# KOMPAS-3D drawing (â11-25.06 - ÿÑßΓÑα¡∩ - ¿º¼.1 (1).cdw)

Views: Вид 1, Выносной элемент
Referenced files in C:\Users\Konstruktor\Documents\Евстигнеева\Архив чертежей\Изделия\Г11-24\: Г11-24.06 - Шестерня.cdw
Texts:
  Шестерня
  Евстигнеева Г.А.
  НПП "Гидропривод"
  Радиус развернутости
  эвольвенты в начале
  рабочего участка профиля
  Допуск на погрешность
  направления зуба
  Контролировать
  при отсутствии
  обкатки с
  измерительной
  шестерней
  Допуск на
  колебание
  измерительного
  межосевого
  расстояния
  Допуск на колебание длины
  общей нормали
  Длина общей нормали
  Делительный диаметр
  Диаметр начальной окружности
  Степень точности
  по ГОСТ 1643-81
  Коэффициент смещения
  Исходный контур
  Число зубьев
  Модуль
  Отклонение
  основного
  шага
  погрешность
  профиля зуба
  радиальное
  биение
  зубчатого
  венца
  На одном
  зубе
  За оборот
  колеса
  f '' pt
  F vw
  ГОСТ 13755-81
  Н,мм
  Номин.
  Пред. отк.
  Таблица параметров
  47...52 HRC Э . Закалка изотермическая.
  Допускается контроль по суммарному пятну контакта с зубьми
  измерительной шестерни:
  по высоте не менее 30%;
  по длине не менее  40%.
  * Размеры для справок.
  Острые кромки скруглить R 0,1 тах.
  gliv
  Евстигнеева
  Сталь 40Х ГОСТ 4543-71
  г.Ярославль
Dimensions and other numbers on the sheet: 8; 0,4; 0,02; 0,8; 2,5; 0,01; 8,57464; 0,016; 0,014; 0,04; 0,025; 0,056; 0,022; 39,88 -0,055 -0,135; 60; 65; 7-C; +0,6252; 12; 5; 75; 2,6; 2 места; 30; 18,6; 53,75; 0,03; 49; 38,75; -0,005; -0,020; 42; 1; 3,2; 1:1; 01.08.2012; 2; 1,8;  30,6   30; 06.03.2013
